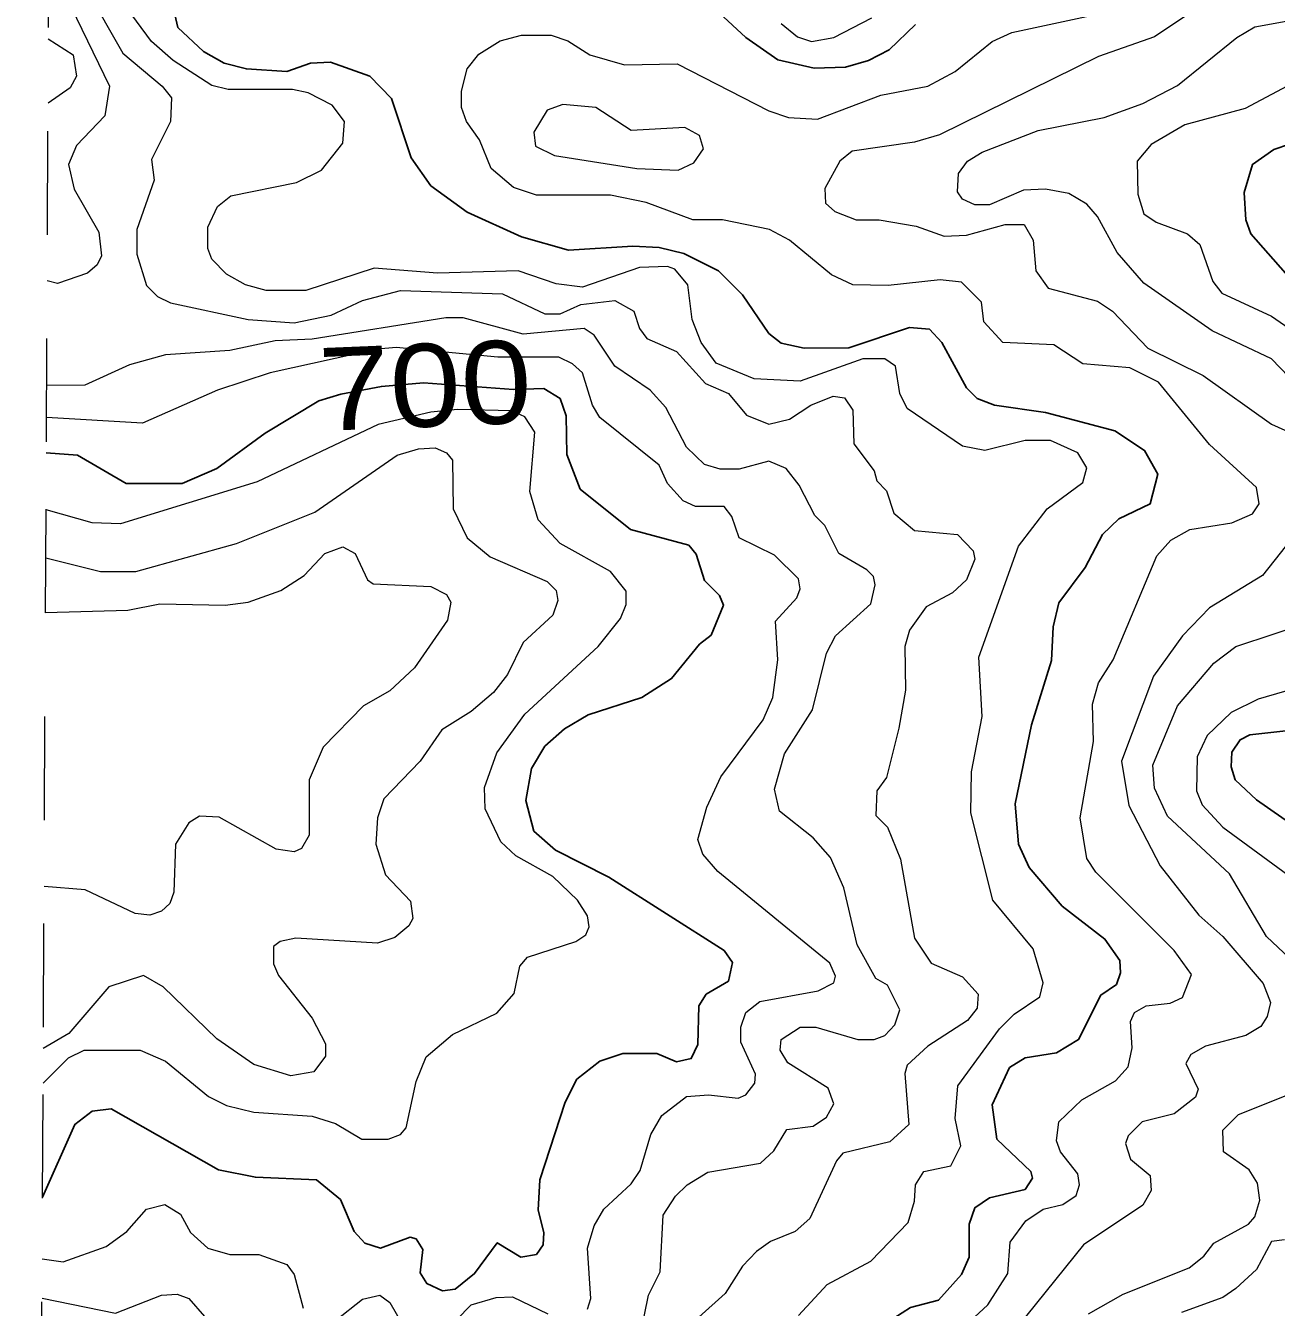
# Model space of a CAD drawing. Extents: x 577 to 602.9, y 7483.8 to 7511.6.
# Drawn here: x 577.007 to 578.214, y 7487.046 to 7488.282 of the extents above; entities that cross this region are included whole.
import ezdxf
from ezdxf.enums import TextEntityAlignment as Align

# ---------------------------------------------------------------- set-up
doc = ezdxf.new("R2010")
doc.units = 0
doc.header["$LTSCALE"] = 0.032
doc.linetypes.add('SHORT_DASHED', pattern=[2.7, 1.5, -1.2])
for name, color, linetype, lineweight in [('1', 7, 'Continuous', 25), ('2', 7, 'Continuous', 13), ('62', 7, 'SHORT_DASHED', 13)]:
    doc.layers.add(name, color=color, linetype=linetype, lineweight=lineweight)
doc.layers.add('61', color=7, linetype='Continuous')

msp = doc.modelspace()

# ---------------------------------------------------------------- linework, layer by layer
at = {"layer": '1'}
for points in [[(577.1426, 7488.3282), (577.1537, 7488.2805), (577.1784, 7488.2574), (577.1983, 7488.2463), (577.2197, 7488.2407), (577.2587, 7488.2383), (577.2817, 7488.2463), (577.3008, 7488.2471), (577.339, 7488.2336), (577.3597, 7488.2121), (577.3788, 7488.1548), (577.3978, 7488.1278), (577.4328, 7488.1024), (577.4853, 7488.0785), (577.5306, 7488.0658), (577.5927, 7488.0697), (577.6181, 7488.0682), (577.642, 7488.0626), (577.6754, 7488.0459), (577.6984, 7488.0228), (577.7239, 7487.9855), (577.7358, 7487.9759), (577.7581, 7487.9711), (577.801, 7487.9714), (577.8598, 7487.991), (577.8789, 7487.9894), (577.8909, 7487.9767), (577.9147, 7487.933), (577.925, 7487.9226), (577.9417, 7487.9163), (577.991, 7487.9091), (578.0578, 7487.8916), (578.0865, 7487.8725), (578.0992, 7487.8495), (578.092, 7487.8209), (578.0618, 7487.8065), (578.0459, 7487.7914), (578.0292, 7487.7596), (578.0038, 7487.7254), (577.9982, 7487.7024), (577.9966, 7487.6698), (577.9775, 7487.6078), (577.9616, 7487.5314), (577.9648, 7487.4925), (577.9751, 7487.4702), (578.0069, 7487.4328), (578.0483, 7487.401), (578.0626, 7487.3803), (578.0634, 7487.3684), (578.0594, 7487.3573), (578.0443, 7487.3469), (578.0229, 7487.304), (578.0014, 7487.2913), (577.9712, 7487.2865), (577.9561, 7487.277), (577.9394, 7487.2412), (577.9441, 7487.2078), (577.9767, 7487.1768), (577.9783, 7487.1704), (577.9712, 7487.1593), (577.937, 7487.1513), (577.9227, 7487.1418), (577.9171, 7487.1259), (577.9171, 7487.0941), (577.9099, 7487.0774), (577.8877, 7487.0527), (577.8606, 7487.0456), (577.8447, 7487.0352)], [(577.8654, 7488.2837), (577.84, 7488.259), (577.8201, 7488.2487), (577.7978, 7488.2423), (577.7676, 7488.2415), (577.7326, 7488.2495), (577.7016, 7488.2709), (577.6674, 7488.3027)], [(578.2224, 7488.0435), (578.189, 7488.0817), (578.1843, 7488.0952), (578.1827, 7488.1214), (578.1906, 7488.1485), (578.2113, 7488.1628), (578.2415, 7488.1731)], [(577.023, 7487.152), (577.0543, 7487.2221), (577.071, 7487.2348), (577.0893, 7487.2372), (577.1927, 7487.1784), (577.2285, 7487.1712), (577.2873, 7487.1688), (577.3104, 7487.1497), (577.3239, 7487.1187), (577.3342, 7487.1076), (577.3493, 7487.1028), (577.3779, 7487.1134), (577.3835, 7487.1116), (577.3899, 7487.1015), (577.3875, 7487.079), (577.3939, 7487.0686), (577.409, 7487.0615), (577.4211, 7487.0632), (577.44, 7487.0782), (577.4619, 7487.108), (577.4845, 7487.0941), (577.4996, 7487.0965), (577.506, 7487.106), (577.5068, 7487.1179), (577.5012, 7487.1394), (577.5028, 7487.1688), (577.5275, 7487.2436), (577.5386, 7487.2658), (577.5609, 7487.2833), (577.5831, 7487.2905), (577.6157, 7487.2905), (577.6348, 7487.2825), (577.6491, 7487.2857), (577.6555, 7487.2992), (577.6563, 7487.3366), (577.6634, 7487.3477), (577.6849, 7487.3605), (577.6888, 7487.3785), (577.6809, 7487.3899), (577.5696, 7487.4606), (577.5179, 7487.4869), (577.4972, 7487.5052), (577.4893, 7487.5346), (577.4949, 7487.5656), (577.5076, 7487.5871), (577.5267, 7487.6038), (577.5497, 7487.6173), (577.6014, 7487.634), (577.63, 7487.6523), (577.6571, 7487.6857), (577.6682, 7487.6944), (577.6801, 7487.7231), (577.6762, 7487.7326), (577.6618, 7487.7469), (577.6539, 7487.7724), (577.6467, 7487.7811), (577.5903, 7487.7962), (577.5418, 7487.8352), (577.529, 7487.8686), (577.5283, 7487.9059), (577.5227, 7487.9226), (577.5068, 7487.9322), (577.4774, 7487.9314), (577.3908, 7487.9376), (577.35, 7487.9343), (577.3109, 7487.9267), (577.2897, 7487.9203), (577.238, 7487.8892), (577.1911, 7487.8551), (577.1577, 7487.8407), (577.1036, 7487.8407), (577.0568, 7487.8679), (577.0266, 7487.8703)], [(578.2574, 7487.4917), (578.1946, 7487.5354), (578.1739, 7487.5545), (578.17, 7487.5672), (578.1708, 7487.5815), (578.1787, 7487.5934), (578.1882, 7487.5982), (578.2256, 7487.6022)]]:
    msp.add_lwpolyline(points, dxfattribs=at)
at = {"layer": '2'}
for points in [[(577.029, 7488.3451), (577.0877, 7488.224), (577.083, 7488.1954), (577.0559, 7488.1668), (577.048, 7488.1485), (577.0535, 7488.1246), (577.0774, 7488.0833), (577.0798, 7488.0602), (577.0758, 7488.0515), (577.0663, 7488.0435), (577.0376, 7488.0336), (577.0275, 7488.0362)], [(577.0655, 7488.3178), (577.1004, 7488.2558), (577.1386, 7488.224), (577.1474, 7488.2129), (577.1466, 7488.1898), (577.1283, 7488.1532), (577.1307, 7488.1334), (577.114, 7488.0857), (577.114, 7488.0618), (577.1235, 7488.0316), (577.1338, 7488.0212), (577.1466, 7488.0149), (577.2213, 7487.999), (577.2658, 7487.9958), (577.3016, 7488.003), (577.3318, 7488.0173), (577.3684, 7488.0268), (577.467, 7488.0236), (577.5076, 7488.0045), (577.5227, 7488.0045), (577.5426, 7488.0133), (577.5752, 7488.0173), (577.5935, 7488.0069), (577.599, 7487.9902), (577.6062, 7487.9807), (577.6347, 7487.9681), (577.6628, 7487.9371), (577.6849, 7487.9274), (577.7024, 7487.9067), (577.7239, 7487.898), (577.7437, 7487.9028), (577.7644, 7487.9163), (577.7859, 7487.925), (577.797, 7487.9234), (577.805, 7487.9115), (577.8058, 7487.8789), (577.8256, 7487.8527), (577.828, 7487.8431), (577.8376, 7487.8336), (577.8447, 7487.8121), (577.8646, 7487.7954), (577.906, 7487.7914), (577.9211, 7487.7755), (577.9227, 7487.7676), (577.9147, 7487.7477), (577.9012, 7487.735), (577.8757, 7487.7215), (577.8598, 7487.6992), (577.8551, 7487.6833), (577.8559, 7487.6411), (577.8495, 7487.6046), (577.8376, 7487.5569), (577.828, 7487.5441), (577.8272, 7487.5203), (577.8384, 7487.5091), (577.8511, 7487.4781), (577.8646, 7487.4018), (577.8805, 7487.3779), (577.9107, 7487.3644), (577.9258, 7487.3477), (577.925, 7487.3342), (577.9155, 7487.3223), (577.8773, 7487.2976), (577.8575, 7487.2793), (577.8551, 7487.2714), (577.8591, 7487.2221), (577.8408, 7487.2054), (577.7954, 7487.1943), (577.7891, 7487.1871), (577.7636, 7487.1314), (577.7493, 7487.1187), (577.7255, 7487.1092), (577.7119, 7487.0996), (577.6984, 7487.0853), (577.6817, 7487.0591), (577.6563, 7487.036)], [(578.1564, 7488.3123), (578.096, 7488.2717), (578.0419, 7488.2526), (577.8885, 7488.1771), (577.8646, 7488.1699), (577.8042, 7488.1612), (577.7923, 7488.1517), (577.7779, 7488.1254), (577.7787, 7488.1111), (577.7875, 7488.1031), (577.8082, 7488.0952), (577.8304, 7488.0952), (577.8662, 7488.0888), (577.8932, 7488.0793), (577.9147, 7488.0801), (577.9521, 7488.0904), (577.9704, 7488.0904), (577.9791, 7488.0753), (577.9815, 7488.0459), (577.9934, 7488.0292), (578.0411, 7488.0165), (578.0555, 7488.0069), (578.0896, 7487.9711), (578.1429, 7487.9449), (578.2089, 7487.898), (578.2741, 7487.8686)], [(577.1283, 7488.267), (577.1036, 7488.3003)], [(577.4853, 7488.2733), (577.5139, 7488.2733), (577.5298, 7488.2677), (577.5513, 7488.2542), (577.5847, 7488.2447), (577.6356, 7488.2455), (577.7239, 7488.2002), (577.743, 7488.1938), (577.7708, 7488.1922), (577.832, 7488.2153), (577.8773, 7488.224), (577.9036, 7488.2383), (577.9394, 7488.267), (577.9584, 7488.2757), (578.0396, 7488.2932)], [(577.7358, 7488.2844), (577.7517, 7488.2717), (577.7652, 7488.267), (577.7867, 7488.2709), (577.8233, 7488.29)], [(578.2511, 7487.9171), (578.2089, 7487.9608), (578.1517, 7487.9878), (578.0857, 7488.034), (578.0602, 7488.0634), (578.0411, 7488.0984), (578.0308, 7488.1103), (578.0133, 7488.1206), (577.991, 7488.1246), (577.9696, 7488.1238), (577.937, 7488.1095), (577.9227, 7488.1095), (577.9107, 7488.1151), (577.906, 7488.1222), (577.9068, 7488.1397), (577.9155, 7488.1517), (577.9298, 7488.1604), (577.9839, 7488.1811), (578.0475, 7488.1938), (578.0849, 7488.2073), (578.1183, 7488.2248), (578.1755, 7488.2709), (578.193, 7488.2813), (578.2232, 7488.2868)], [(577.0286, 7488.2696), (577.0527, 7488.2542), (577.0559, 7488.2336), (577.0496, 7488.2224), (577.0283, 7488.2075)], [(577.7525, 7487.0376), (577.7803, 7487.0678), (577.8225, 7487.0901), (577.8583, 7487.1275), (577.8646, 7487.1481), (577.8654, 7487.164), (577.8734, 7487.1768), (577.8996, 7487.1823), (577.9091, 7487.2014), (577.9036, 7487.2277), (577.9064, 7487.2593), (577.9465, 7487.3143), (577.9608, 7487.3286), (577.9855, 7487.3453), (577.9887, 7487.3589), (577.9791, 7487.3915), (577.9402, 7487.4384), (577.9187, 7487.5227), (577.9195, 7487.5624), (577.9298, 7487.6157), (577.9266, 7487.673), (577.9648, 7487.7803), (577.9926, 7487.8161), (578.0268, 7487.8415), (578.0308, 7487.8558), (578.0221, 7487.8702), (577.9958, 7487.8821), (577.9712, 7487.8821), (577.9322, 7487.8725), (577.9107, 7487.8765), (577.8575, 7487.9131), (577.8503, 7487.9274), (577.8463, 7487.9537), (577.836, 7487.9608), (577.8145, 7487.9608), (577.7541, 7487.9393), (577.7096, 7487.9417), (577.673, 7487.9568), (577.6587, 7487.9767), (577.6499, 7487.999), (577.6459, 7488.0324), (577.6332, 7488.0475), (577.6261, 7488.0499), (577.599, 7488.0491), (577.5442, 7488.03), (577.5187, 7488.0332), (577.4821, 7488.0459), (577.4042, 7488.0435), (577.343, 7488.0483), (577.277, 7488.0268), (577.2388, 7488.0268), (577.2189, 7488.0324), (577.2006, 7488.0427), (577.1863, 7488.057), (577.1824, 7488.0674), (577.1824, 7488.088), (577.1919, 7488.1079), (577.2046, 7488.1183), (577.2682, 7488.131), (577.2921, 7488.1429), (577.3128, 7488.1691), (577.3144, 7488.1898), (577.3024, 7488.2057), (577.2794, 7488.2177), (577.2643, 7488.2208), (577.2022, 7488.2208), (577.1863, 7488.2248), (577.149, 7488.2487), (577.1283, 7488.267)], [(577.8845, 7487.001), (577.9354, 7487.0479), (577.9545, 7487.0782), (577.9569, 7487.1084), (577.972, 7487.1291), (577.9887, 7487.1402), (578.0077, 7487.145), (578.0205, 7487.1537), (578.0236, 7487.164), (578.0221, 7487.1744), (578.0054, 7487.1958), (578.0014, 7487.2062), (578.0038, 7487.2245), (578.026, 7487.2459), (578.0586, 7487.2642), (578.0706, 7487.2778), (578.0745, 7487.296), (578.0729, 7487.3215), (578.0769, 7487.3302), (578.0881, 7487.3366), (578.1111, 7487.339), (578.123, 7487.3445), (578.1318, 7487.3668), (578.1151, 7487.3899), (578.0396, 7487.4654), (578.0308, 7487.4789), (578.0244, 7487.5179), (578.0372, 7487.5918), (578.0364, 7487.6276), (578.0419, 7487.6483), (578.0563, 7487.6706), (578.0984, 7487.7708), (578.1119, 7487.7859), (578.1302, 7487.7962), (578.1708, 7487.8026), (578.1906, 7487.8113), (578.197, 7487.8209), (578.1946, 7487.8368), (578.1493, 7487.8781), (578.1, 7487.9385), (578.0722, 7487.9521), (578.0268, 7487.956), (577.999, 7487.9743), (577.9497, 7487.9767), (577.9314, 7487.9966), (577.929, 7488.0157), (577.9099, 7488.0348), (577.8893, 7488.0371), (577.8392, 7488.0316), (577.805, 7488.0324), (577.7843, 7488.0419), (577.7437, 7488.0753), (577.7247, 7488.0857), (577.6793, 7488.0952), (577.6507, 7488.0952), (577.6054, 7488.1119), (577.5712, 7488.119), (577.4996, 7488.119), (577.4774, 7488.1262), (577.4559, 7488.1445), (577.4448, 7488.1723), (577.432, 7488.1898), (577.4273, 7488.2033), (577.4273, 7488.2192), (577.4328, 7488.2407), (577.444, 7488.255), (577.4646, 7488.2677), (577.4853, 7488.2733)], [(578.224, 7488.224), (578.1835, 7488.2025), (578.1254, 7488.1866), (578.0928, 7488.1676), (578.0793, 7488.1517), (578.0801, 7488.1198), (578.0857, 7488.1008), (578.0976, 7488.0928), (578.1278, 7488.0817), (578.1397, 7488.0713), (578.1525, 7488.0356), (578.1612, 7488.0244), (578.2089, 7488.0022), (578.255, 7487.9704)], [(577.5998, 7487.0177), (577.6078, 7487.0575), (577.6189, 7487.0798), (577.6221, 7487.1346), (577.634, 7487.1529), (577.6451, 7487.164), (577.665, 7487.176), (577.7159, 7487.1847), (577.7286, 7487.1966), (577.7414, 7487.2173), (577.7668, 7487.2205), (577.7795, 7487.2292), (577.7867, 7487.242), (577.7811, 7487.2571), (577.7422, 7487.2817), (577.735, 7487.2937), (577.7358, 7487.304), (577.7541, 7487.3159), (577.7692, 7487.3159), (577.8097, 7487.304), (577.8256, 7487.304), (577.836, 7487.308), (577.8455, 7487.3183), (577.8503, 7487.3326), (577.8384, 7487.3565), (577.8272, 7487.3628), (577.809, 7487.3954), (577.7962, 7487.4503), (577.7835, 7487.4797), (577.7668, 7487.4988), (577.7342, 7487.5243), (577.7294, 7487.5457), (577.739, 7487.5799), (577.766, 7487.6221), (577.7795, 7487.6769), (577.7883, 7487.6936), (577.8225, 7487.7246), (577.8264, 7487.7429), (577.8249, 7487.7509), (577.8185, 7487.7572), (577.7915, 7487.7731), (577.7779, 7487.8002), (577.7684, 7487.8097), (577.7533, 7487.8391), (577.7406, 7487.8551), (577.7239, 7487.8622), (577.6952, 7487.8543), (577.677, 7487.8543), (577.6618, 7487.859), (577.6443, 7487.8757), (577.6245, 7487.9139), (577.6094, 7487.9306), (577.5752, 7487.9537), (577.5553, 7487.9839), (577.5457, 7487.9902), (577.4869, 7487.9847), (577.4289, 7488.0006), (577.4122, 7488.0006), (577.2833, 7487.9799), (577.2476, 7487.9783), (577.2038, 7487.9688), (577.1418, 7487.9648), (577.1068, 7487.9552), (577.0639, 7487.9354), (577.027, 7487.9351)], [(577.5489, 7487.044), (577.5521, 7487.0543), (577.5489, 7487.1028), (577.5553, 7487.1243), (577.5648, 7487.1402), (577.5911, 7487.1648), (577.5998, 7487.1776), (577.6102, 7487.2125), (577.6205, 7487.2308), (577.6443, 7487.2491), (577.6658, 7487.2507), (577.6944, 7487.2475), (577.7016, 7487.2507), (577.7103, 7487.2618), (577.7111, 7487.2706), (577.6968, 7487.3016), (577.6968, 7487.3159), (577.7016, 7487.3302), (577.7151, 7487.3406), (577.7716, 7487.3509), (577.7867, 7487.3589), (577.7883, 7487.3652), (577.7827, 7487.3779), (577.6746, 7487.4662), (577.6603, 7487.4829), (577.6555, 7487.4972), (577.6642, 7487.5282), (577.6777, 7487.5577), (577.7183, 7487.6125), (577.7278, 7487.634), (577.7326, 7487.6706), (577.7302, 7487.7079), (577.7509, 7487.7302), (577.7541, 7487.739), (577.7525, 7487.7485), (577.7294, 7487.7716), (577.6952, 7487.7883), (577.6881, 7487.8089), (577.6809, 7487.8185), (577.6531, 7487.8185), (577.6412, 7487.824), (577.6261, 7487.8407), (577.6181, 7487.8582), (577.5609, 7487.9044), (577.5537, 7487.9163), (577.5442, 7487.9473), (577.5346, 7487.956), (577.5211, 7487.9624), (577.4623, 7487.9624), (577.3644, 7487.9719), (577.3462, 7487.9704), (577.2428, 7487.9473), (577.1919, 7487.9306), (577.1195, 7487.8988), (577.0268, 7487.9043)], [(577.0235, 7487.262), (577.048, 7487.2865), (577.0631, 7487.2937), (577.1171, 7487.2937), (577.1418, 7487.2833), (577.1831, 7487.2491), (577.2006, 7487.2404), (577.2269, 7487.234), (577.2833, 7487.23), (577.3056, 7487.2229), (577.331, 7487.2078), (577.3565, 7487.2078), (577.3684, 7487.2125), (577.374, 7487.2189), (577.3835, 7487.2634), (577.3931, 7487.2873), (577.4185, 7487.3088), (577.4615, 7487.3294), (577.4782, 7487.3485), (577.4837, 7487.3748), (577.4909, 7487.3835), (577.5378, 7487.3986), (577.5473, 7487.405), (577.5505, 7487.4129), (577.5489, 7487.4233), (577.5394, 7487.4384), (577.5155, 7487.4614), (577.4797, 7487.4813), (577.4654, 7487.4948), (577.4503, 7487.5266), (577.4495, 7487.5473), (577.4615, 7487.5807), (577.4885, 7487.6181), (577.5593, 7487.6833), (577.5807, 7487.7103), (577.5863, 7487.7238), (577.5863, 7487.7366), (577.5712, 7487.7557), (577.5227, 7487.7827), (577.5012, 7487.8057), (577.4933, 7487.8328), (577.498, 7487.89), (577.4885, 7487.9051), (577.4758, 7487.9107), (577.4236, 7487.9121), (577.3977, 7487.9095), (577.3469, 7487.8977), (577.2301, 7487.8423), (577.0981, 7487.8018), (577.071, 7487.8026), (577.0264, 7487.8152)], [(577.0261, 7487.7689), (577.079, 7487.7557), (577.1132, 7487.7557), (577.2102, 7487.7827), (577.2857, 7487.8129), (577.3652, 7487.8678), (577.3859, 7487.8741), (577.4018, 7487.8749), (577.413, 7487.8702), (577.4185, 7487.863), (577.4193, 7487.8161), (577.4328, 7487.7883), (577.4551, 7487.77), (577.51, 7487.7461), (577.5187, 7487.7374), (577.5203, 7487.7278), (577.5155, 7487.7135), (577.4869, 7487.6873), (577.4718, 7487.6563), (577.4583, 7487.6388), (577.4368, 7487.6205), (577.4082, 7487.603), (577.3875, 7487.5728), (577.3525, 7487.5362), (577.3462, 7487.5179), (577.3446, 7487.4925), (577.3541, 7487.463), (577.378, 7487.4376), (577.3804, 7487.4209), (577.3764, 7487.4137), (577.3629, 7487.4026), (577.3462, 7487.397), (577.2674, 7487.4018), (577.2523, 7487.3986), (577.246, 7487.3938), (577.246, 7487.3772), (577.2507, 7487.366), (577.2833, 7487.3247), (577.2961, 7487.3), (577.2961, 7487.2881), (577.2849, 7487.273), (577.2627, 7487.269), (577.2269, 7487.2801), (577.1911, 7487.3048), (577.1394, 7487.3549), (577.1203, 7487.366), (577.0869, 7487.3549), (577.0483, 7487.3099), (577.0237, 7487.2953)], [(578.2455, 7487.8089), (578.2002, 7487.7517), (578.1493, 7487.7207), (578.123, 7487.6936), (578.0952, 7487.6547), (578.0642, 7487.5728), (578.0714, 7487.5298), (578.1016, 7487.4718), (578.1389, 7487.4241), (578.162, 7487.4034), (578.201, 7487.3581), (578.2081, 7487.3398), (578.2049, 7487.3263), (578.1986, 7487.3167), (578.1843, 7487.308), (578.1453, 7487.2976), (578.131, 7487.2897), (578.1262, 7487.2809), (578.1382, 7487.2563), (578.1358, 7487.2483), (578.1151, 7487.2324), (578.0841, 7487.2245), (578.0706, 7487.211), (578.0682, 7487.2038), (578.0729, 7487.1887), (578.092, 7487.1728), (578.0928, 7487.1585), (578.0849, 7487.1442), (578.0276, 7487.106), (577.9449, 7487.0034)], [(577.0259, 7487.7162), (577.1052, 7487.7183), (577.1362, 7487.7246), (577.1991, 7487.7231), (577.2213, 7487.7262), (577.2531, 7487.7374), (577.2754, 7487.7517), (577.2953, 7487.7731), (577.3128, 7487.7795), (577.3247, 7487.7731), (577.3366, 7487.7477), (577.3422, 7487.7437), (577.3978, 7487.7413), (577.413, 7487.7334), (577.4169, 7487.7262), (577.4137, 7487.7087), (577.3819, 7487.6626), (577.3581, 7487.6404), (577.3326, 7487.626), (577.2937, 7487.5863), (577.2802, 7487.5545), (577.2802, 7487.5012), (577.273, 7487.4885), (577.2658, 7487.4853), (577.2484, 7487.4877), (577.1935, 7487.5187), (577.1744, 7487.5195), (577.1641, 7487.5131), (577.1513, 7487.4925), (577.1497, 7487.4463), (577.1458, 7487.4352), (577.1378, 7487.428), (577.1267, 7487.4241), (577.1124, 7487.4257), (577.0643, 7487.4485), (577.0245, 7487.4518)], [(578.2702, 7487.3414), (578.2042, 7487.4034), (578.1684, 7487.4638), (578.1087, 7487.5195), (578.096, 7487.5465), (578.0944, 7487.5688), (578.1183, 7487.626), (578.1533, 7487.6674), (578.1747, 7487.6833), (578.2487, 7487.7079)], [(578.3131, 7487.6666), (578.1962, 7487.6324), (578.17, 7487.6197), (578.1469, 7487.5974), (578.1374, 7487.5767), (578.1366, 7487.5441), (578.1421, 7487.5306), (578.162, 7487.5091), (578.2344, 7487.4559)], [(578.0324, 7487.0392), (578.0658, 7487.0583), (578.1294, 7487.0837), (578.1437, 7487.0949), (578.1533, 7487.1076), (578.1867, 7487.1259), (578.193, 7487.133), (578.1978, 7487.1489), (578.1954, 7487.1656), (578.1875, 7487.1784), (578.1628, 7487.1958), (578.162, 7487.2165), (578.1771, 7487.2316), (578.2248, 7487.2507)], [(577.0227, 7487.0924), (577.043, 7487.0895), (577.0845, 7487.1044), (577.1044, 7487.1187), (577.1235, 7487.1402), (577.141, 7487.145), (577.1561, 7487.1354), (577.1657, 7487.1179), (577.1824, 7487.1028), (577.2038, 7487.0965), (577.2317, 7487.0965), (577.2587, 7487.0869), (577.2658, 7487.0774), (577.2746, 7487.0448)], [(578.2216, 7487.1108), (578.2089, 7487.1092), (578.1946, 7487.0821), (578.1747, 7487.0639)], [(578.1747, 7487.0639), (578.162, 7487.0551), (578.1222, 7487.0408)], [(577.0225, 7487.0545), (577.0933, 7487.04), (577.1378, 7487.0575), (577.1529, 7487.0583), (577.1641, 7487.0543), (577.1792, 7487.0368)], [(577.3056, 7487.0328), (577.3318, 7487.0535), (577.3485, 7487.0575), (577.3581, 7487.0503), (577.3692, 7487.0312)], [(577.4225, 7487.0336), (577.4368, 7487.0479), (577.4607, 7487.0551), (577.4766, 7487.0559), (577.5108, 7487.0392)]]:
    msp.add_lwpolyline(points, dxfattribs=at)
msp.add_lwpolyline([(577.5171, 7488.1572), (577.5966, 7488.1445), (577.6364, 7488.1429), (577.6515, 7488.1501), (577.661, 7488.1636), (577.6571, 7488.1763), (577.6428, 7488.1843), (577.5911, 7488.1811), (577.5569, 7488.2033), (577.5251, 7488.2065), (577.51, 7488.201), (577.4972, 7488.1795), (577.4988, 7488.166)], close=True, dxfattribs=at)
at = {"layer": '62'}
msp.add_lwpolyline([(577.0067, 7483.927), (577.0095, 7484.4918), (577.0124, 7485.0566), (577.0152, 7485.6214), (577.0181, 7486.1863), (577.0209, 7486.7511), (577.0238, 7487.3159), (577.0267, 7487.8807), (577.0295, 7488.4455), (577.0324, 7489.0103), (577.0352, 7489.5752), (577.0381, 7490.14), (577.0409, 7490.7048), (577.0438, 7491.2696), (577.0466, 7491.8344), (577.0495, 7492.3992), (577.0523, 7492.9641)], dxfattribs=at)

# ---------------------------------------------------------------- texts
at = {"layer": '61', "width": 1.15}
msp.add_text('700', height=0.08, rotation=2.338, dxfattribs=at).set_placement((577.3939, 7487.8954), align=Align.CENTER)

doc.saveas('drawing.dxf')
